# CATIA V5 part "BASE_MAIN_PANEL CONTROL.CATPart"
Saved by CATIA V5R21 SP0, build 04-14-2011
Part number: BASE_MAIN_PANEL CONTROL
Bounding box of the stored display mesh (mm): x -5 to 46, y -45.5 to 45.5, z -21.5 to 21.5
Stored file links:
  D:\MENA 3D\BISMARK\BASE_MAIN_PANEL CONTROL.CATPart
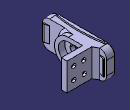
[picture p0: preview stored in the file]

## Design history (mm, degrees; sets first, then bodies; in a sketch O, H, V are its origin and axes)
Body1 (main body)
  Sketch1 on yz-plane, origin (0, 0, 0), H (0, 1, 0), V (0, 0, 1)
    line L1 (45.5, 9.5) -> (45.5, -9.5)
    line L2 (35.5, -19.5) -> (-35.5, -19.5)
    line L3 (-45.5, -9.5) -> (-45.5, 9.5)
    line L4 (-35.5, 19.5) -> (35.5, 19.5)
    circle A1 centre (0, 0) radius 6
    arc A2 centre (-35.5, 9.5) radius 10 from (-45.5, 9.5) to (-35.5, 19.5) cw
    arc A3 centre (35.5, 9.5) radius 10 from (45.5, 9.5) to (35.5, 19.5) ccw
    arc A4 centre (-35.5, -9.5) radius 10 from (-35.5, -19.5) to (-45.5, -9.5) cw
    arc A5 centre (35.5, -9.5) radius 10 from (45.5, -9.5) to (35.5, -19.5) cw
    distance L3 L1 = 91
    distance L4 L2 = 39
    radius A2 = 10
    radius A3 = 10
    radius A4 = 10
    radius A5 = 10
    radius A1 = 6
    vertical: L1 V, L3 V
    horizontal: L2 H, L4 H
    equidistance: L1 L3 O, L2 L4 O
    tangency: A2 L3, A2 L4, A3 L1, A3 L4, A4 L2, A4 L3, A5 L1, A5 L2
  Pad1: profile Sketch1, direction (1, 0, 0), length 7, opposite side length 5
  DatumCurve1
  Sketch2 on end face of Pad1, origin (7, 0, 0), H (0, 1, 0), V (0, 0, 1)
    point P1 (24.3347, 0)
    line L1 (28.3347, 19.5) -> (28.3347, -19.5)
    line L2 (28.3347, -19.5) -> (20.3347, -19.5)
    line L3 (20.3347, -19.5) -> (20.3347, 19.5)
    line L4 (20.3347, 19.5) -> (28.3347, 19.5)
    reference projected line E1 (-35.75, -19.5) -> (35.75, -19.5) from edge [face of Pad1 from Sketch1.L2 | end face of Pad1]
    reference projected point E2 (20.3347, 13.7477) from edge of DatumCurve1
    distance L1 L3 = 8
    coincidence: P1 H, L2 E1, L3 E2
    vertical: L1 V, L3 V
    horizontal: L2 H, L4 H
    equidistance: L1 L3 P1, L2 L4 P1
  Pad2: profile Sketch2, direction (1, 0, 0), length 39
  DatumCurve2
  DatumCurve3
  Sketch3 on face of Pad2 from Sketch2.L1, origin (27.0975, 28.3347, 7.0198), H (1, 0, 0), V (0, 0, -1)
    point P1 (9.4025, 15.3069)
    reference projected curve E1 from edge of DatumCurve3
    concentricity: P1 E1
  Hole1: placed by Sketch3, at (36.5, 28.3347, -8.2871) direction (0, -1, 0), diameter 3, depth 10, counterbore diameter 6, counterbore depth 3
  DatumCurve4
  DatumCurve5
  Sketch4 on face of Pad2 from Sketch2.L1, origin (31.4721, 28.3347, 8.7806), H (1, 0, 0), V (0, 0, -1)
    point P1 (5.0279, 0.069)
    reference projected curve E1 from edge of DatumCurve5
    concentricity: P1 E1
  Hole2: placed by Sketch4, at (36.5, 28.3347, 8.7117) direction (0, -1, 0), diameter 3, depth 10, counterbore diameter 6, counterbore depth 3
  DatumCurve6 to DatumCurve8
  Sketch5 on face of Pad2 from Sketch2.L1, origin (20.0246, 28.3347, 8.408), H (1, 0, 0), V (0, 0, -1)
    point P1 (2.4754, -0.3036)
    reference projected curve E1 from edge of DatumCurve8
    concentricity: P1 E1
  Hole3: placed by Sketch5, at (22.5, 28.3347, 8.7117) direction (0, -1, 0), diameter 3, depth 10, counterbore diameter 6, counterbore depth 3
  DatumCurve9
  DatumCurve10
  Sketch6 on face of Pad2 from Sketch2.L1, origin (19.7433, 28.3347, -12.5059), H (1, 0, 0), V (0, 0, -1)
    point P1 (1.7567, -4.2188)
    reference projected curve E1 from edge of DatumCurve10
    concentricity: P1 E1
  Hole4: placed by Sketch6, at (21.5, 28.3347, -8.2871) direction (0, -1, 0), diameter 3, depth 10, counterbore diameter 6, counterbore depth 3
  Sketch7 on face of Pad2, origin (0, 0, 19.5), H (1, 0, 0), V (0, 1, 0)
    point P1 (-1.75, 35)
    line L1 (-1.75, 35) -> (-5, 35)
    line L2 (-5, 35) -> (-5, -35)
    line L3 (-5, -35) -> (-1.75, -35)
    point P4 (-1.75, -35)
    reference projected line E1 (-5, 35.5) -> (-5, -35.5) from edge [start face of Pad1 | face of Pad1 from Sketch1.L4]
    spline S1 through (-1.75, 35) (1.5, 0) (-1.75, -35)
    point P5 (-1.75, 35)
    point P6 (1.5, 0)
    point P7 (-1.75, -35)
    distance P6 L2 = 6.5
    distance L1 L3 = 70
    length L3 = 3.25
    length L1 = 3.25
    horizontal: L1 H, L3 H
    vertical: L2 V
    coincidence: L2 E1, P5 P1, P6 H, P7 P4
    symmetry: L3 L1 H
  Pad3: profile Sketch7, direction (0, 0, 1), length 2
  Chamfer1: length 2, angle 45, on edge [face of Pad3 from Sketch7.L3 | end face of Pad3]; edge [face of Pad3 from Sketch7.L1 | end face of Pad3]; edge [face of Pad3 | end face of Pad3]
  Sketch8 on face of Pad2, origin (0, 0, -19.5), H (1, 0, 0), V (0, -1, 0)
    point P1 (-5, 31.5)
    line L1 (-5, 31.5) -> (-5, -31.5)
    point P2 (-5, -31.5)
    spline S1 through (-5, 31.5) (-2, 0) (-5, -31.5)
    reference projected line E1 (-5, 35.5) -> (-5, -35.5) from edge [start face of Pad1 | face of Pad1 from Sketch1.L2]
    point P3 (-5, 31.5)
    point P4 (-2, 0)
    point P5 (-5, -31.5)
    distance P4 L1 = 3
    length L1 = 63
    vertical: L1 V
    coincidence: P3 P1, P4 H, P5 L1, P5 P2, L1 E1
    symmetry: P3 P5 H
  Pad4: profile Sketch8, direction (0, 0, -1), length 2
  Chamfer2: length 2, angle 45, on edge [face of Pad4 | end face of Pad4]
  Chamfer3: length 1, angle 45, on edge [face of Pad4 | face of Pad1 from Sketch1.A3]; edge [face of Pad4 | face of Pad1 from Sketch1.L1]; edge [face of Pad4 | face of Pad1 from Sketch1.A5]; edge [face of Pad4 | face of Pad2] (x2); edge [face of Pad4 | face of Pad1 from Sketch1.A4]; edge [face of Pad4 | face of Pad1 from Sketch1.L3]; edge [face of Pad4 | face of Pad1 from Sketch1.A2]
  Sketch9 on face of Pad4, origin (-5, 0, 0), H (0, -1, 0), V (0, 0, 1)
    circle A1 centre (0, 0) radius 14.5
    radius A1 = 14.5
  Pocket1: profile Sketch9, direction (1, 0, 0), length 6
  Chamfer4: length 7, angle 30, on edge [end face of Pad1 | face of Pad2 from Sketch2.L1]
  Sketch10 on end face of Pad1, origin (7, 0, 0), H (0, 1, 0), V (0, 0, 1)
    point P1 (20.3347, 13.65)
    line L1 (20.3347, 13.65) -> (20.3347, 19.5)
    line L2 (20.3347, 19.5) -> (0.3347, 19.5)
    arc A1 centre (0.3347, 0) radius 19.5 from (0.3347, 19.5) to (0.3347, -19.5) ccw
    line L3 (0.3347, -19.5) -> (20.3347, -19.5)
    point P6 (20.3347, -19.5)
    line L4 (20.3347, -19.5) -> (20.3347, -13.65)
    line L5 (20.3347, -13.65) -> (-0.1653, -13.65)
    arc A2 centre (-0.1653, 0) radius 13.65 from (-0.1653, -13.65) to (-0.1653, 13.65) cw
    line L6 (-0.1653, 13.65) -> (20.3347, 13.65)
    point P11 (20.3347, 13.65)
    reference projected line E1 (35.5, 19.5) -> (-35.5, 19.5) from edge [face of Pad2 | end face of Pad1]
    reference projected line E2 (-35.5, -19.5) -> (35.5, -19.5) from edge [face of Pad2 | end face of Pad1]
    reference projected line E3 (20.3347, 19.5) -> (20.3347, -19.5) from edge [end face of Pad1 | face of Pad2 from Sketch2.L3]
    distance L5 L3 = 5.85
    length L5 = 20.5
    length L2 = 20
    vertical: L1 V, L4 V
    horizontal: L2 H, L5 H
    tangency: A1 L2, L3 A1, A2 L5, L6 A2
    coincidence: P6 L1, P11 L1, P1 P11, L2 E1, L3 E2, L4 E3
    symmetry: L5 L6 H
  Pad5: profile Sketch10, direction (1, 0, 0), length 9
  Sketch11 on xy-plane, origin (0, 0, 0), H (1, 0, 0), V (0, 1, 0)
    line L1 (7, 42.3347) -> (9, 44.0129)
    line L2 (9, 44.0129) -> (9, 41.0129)
    line L3 (9, 41.0129) -> (7, 35.3347)
    point P4 (7, 35.3347)
    line L4 (7, 35.3347) -> (7, 42.3347)
    reference intersected line E1 through (7, 0) direction (0, 1) from end face of Pad1
    reference intersected line E2 through (7, 0) direction (0, 1) from end face of Pad1
    reference projected point E3 (7, 35.3347) from edge [face of Chamfer4 | end face of Pad1]
    angle L1 E2 = 50
    distance L2 L4 = 2
    length L4 = 7
    length L2 = 3
    vertical: L2 V, L4 V
    coincidence: L4 E1, P4 E3
  Pad6: profile Sketch11, direction (0, 0, 1), length 11, mirrored extent
  Fillet1: radius 0.35, on edge [face of Pad6 from Sketch11.L1 | face of Pad6 from Sketch11.L2]
  Mirror1: of Pad6, Fillet1, about zx-plane
  Chamfer5: length 4, angle 30, on edge [end face of Pad1 | face of Pad5 from Sketch10.A1]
